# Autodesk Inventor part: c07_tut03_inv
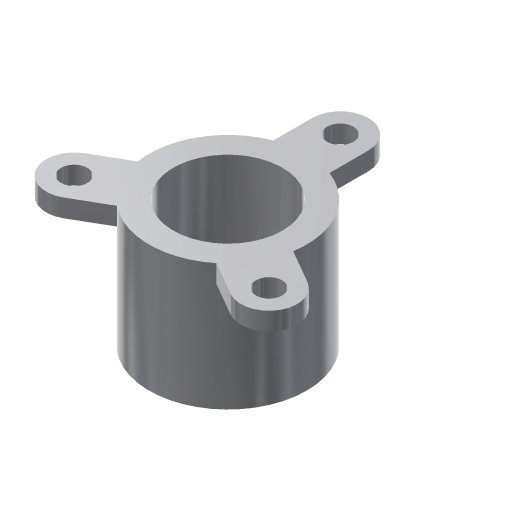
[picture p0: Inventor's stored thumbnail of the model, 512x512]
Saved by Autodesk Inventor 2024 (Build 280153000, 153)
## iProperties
Created: 2010-03
Part Number: c07_tut03_inv
Document SubType Name: Modeling
Designer: CADSoft
Density: 1 g/cm^3
Material: Generic
Appearance: Default
Author: CADSoft
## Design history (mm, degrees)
sketch "Sketch1"
  geometry: C1 r 97 at (0, 0); C2 r 140 at (0, 0); 1 further point
  constraints: 2 centre point, 2 coincident
  dimensions: "d0" = 194 diameter of C1; "d1" = 280 diameter of C2
extrude "Extrusion1" new body sketch "Sketch1" stored distance "d2" = 225; taper "d3" = 0 deg
pattern_circular "Circular Pattern2" dims angle "d38" = 360 deg
body "Solid1"
sketch "Sketch5"
  geometry: L1 (-50, 200)-(-50, 130.767); L2 (50, 200)-(50, 130.767); L3 (0, 0)-(0, 306.095); C1 r 97 at (0, 0) reference; C2 r 23.5 at (0, 200); A1 r 140 centre (0, 0) between (-50, 130.767) and (50, 130.767) reference; A2 r 50 centre (0, 200) between (50, 200) and (-50, 200); A3 r 140 centre (0, 0) between (50, 130.767) and (-50, 130.767)
  constraints: 7 point on circle, 6 end point, 3 centre point, 2 coincident, 2 tangent, 1 other
  dimensions: "d32" = 200 distance of A2.centre C1.centre; "d33" = 50 radius of A2; "d34" = 47 diameter of C2
extrude "Extrusion2" join sketch "Sketch5" distance "d35" = 32; taper "d36" = 0 deg
